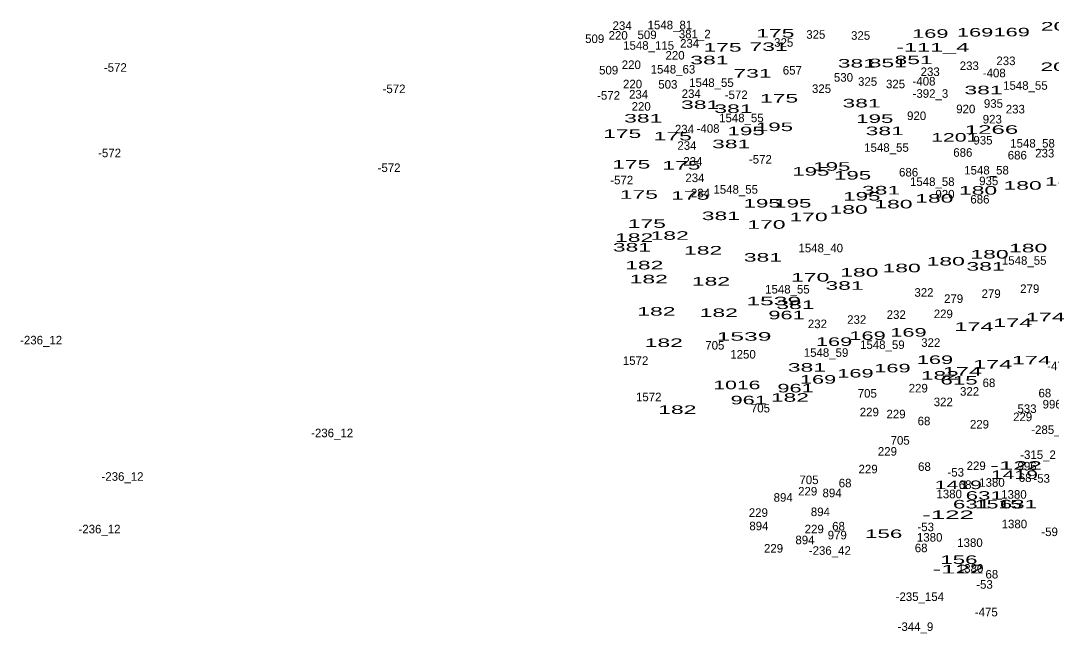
# Model space of a CAD drawing. Extents: x -660434 to -656144, y -997850 to -994016.
# Drawn here: x -658899.6 to -658418.1, y -996780.7 to -996494.1 of the extents above; entities that cross this region are included whole.
import ezdxf
from ezdxf.enums import TextEntityAlignment as Align

# ---------------------------------------------------------------- set-up
doc = ezdxf.new("R2010")
doc.units = 0
doc.header["$LTSCALE"] = 1.6
doc.layers.add('24', color=7, linetype='Continuous')

msp = doc.modelspace()

# ---------------------------------------------------------------- texts
at = {"layer": '24'}
for s, p in [('234', (-658618.631, -996498.49)), ('1548_81', (-658596.316, -996498.19)), ('220', (-658620.491, -996503.04)), ('509', (-658606.977, -996502.78)), ('381_2', (-658584.709, -996502.41)), ('325', (-658528.167, -996502.62)), ('325', (-658507.237, -996503.1)), ('509', (-658631.457, -996504.61)), ('1548_115', (-658606.27, -996507.76)), ('234', (-658587.101, -996506.76)), ('325', (-658543.147, -996506.37)), ('220', (-658593.901, -996512.36)), ('220', (-658614.341, -996516.77)), ('233', (-658456.467, -996517.26)), ('233', (-658439.357, -996514.95)), ('-572', (-658855.371, -996518.06)), ('509', (-658624.937, -996519.31)), ('1548_63', (-658594.887, -996518.87)), ('657', (-658539.128, -996519.38)), ('233', (-658474.727, -996520.05)), ('-408', (-658444.803, -996520.64)), ('220', (-658613.771, -996525.8)), ('503', (-658597.271, -996525.95)), ('1548_55', (-658576.902, -996525.14)), ('530', (-658515.231, -996522.69)), ('325', (-658503.977, -996524.62)), ('325', (-658490.917, -996525.77)), ('-408', (-658477.633, -996524.48)), ('1548_55', (-658430.252, -996526.48)), ('-572', (-658725.191, -996528.04)), ('-572', (-658624.961, -996531.12)), ('234', (-658610.941, -996530.59)), ('234', (-658586.341, -996530.3)), ('-572', (-658565.341, -996530.83)), ('325', (-658525.487, -996527.98)), ('-392_3', (-658474.628, -996530.23)), ('220', (-658609.741, -996536.27)), ('935', (-658445.183, -996534.89)), ('1548_55', (-658562.922, -996541.65)), ('920', (-658481.067, -996540.63)), ('920', (-658458.107, -996537.45)), ('233', (-658434.957, -996537.54)), ('-408', (-658578.483, -996546.57)), ('923', (-658445.703, -996542.24)), ('234', (-658589.531, -996546.87)), ('234', (-658588.371, -996554.56)), ('1548_55', (-658495.142, -996555.48)), ('935', (-658450.073, -996552.08)), ('1548_58', (-658426.922, -996553.5)), ('-572', (-658858.061, -996558.01)), ('-572', (-658554.051, -996560.98)), ('686', (-658459.478, -996557.81)), ('686', (-658434.038, -996559.06)), ('233', (-658421.217, -996558.12)), ('-572', (-658727.501, -996564.92)), ('234', (-658585.581, -996561.96)), ('-572', (-658618.821, -996570.69)), ('234', (-658584.631, -996569.66)), ('686', (-658484.818, -996567.03)), ('1548_58', (-658448.412, -996566.08)), ('1548_55', (-658565.572, -996575.08)), ('1548_58', (-658473.752, -996571.45)), ('935', (-658447.383, -996571.1)), ('234', (-658582.041, -996576.78)), ('920', (-658467.817, -996577.31)), ('686', (-658451.508, -996579.66)), ('1548_40', (-658525.861, -996602.5)), ('1548_55', (-658430.822, -996608.3)), ('1548_55', (-658541.422, -996621.75)), ('322', (-658477.637, -996623.26)), ('279', (-658428.218, -996621.48)), ('279', (-658463.788, -996626.14)), ('279', (-658446.248, -996623.81)), ('229', (-658468.603, -996633.26)), ('232', (-658527.407, -996637.94)), ('232', (-658509.047, -996635.92)), ('232', (-658490.587, -996633.61)), ('-236_12', (-658890.041, -996645.54)), ('1548_59', (-658497.067, -996647.7)), ('322', (-658474.467, -996646.69)), ('705', (-658575.327, -996647.96)), ('1250', (-658562.154, -996652.17)), ('1548_59', (-658523.377, -996651.35)), ('1572', (-658612.356, -996655.11)), ('-475', (-658414.735, -996657.65)), ('68', (-658447.273, -996665.5)), ('705', (-658504.117, -996670.43)), ('229', (-658480.313, -996668.01)), ('322', (-658456.327, -996669.53)), ('68', (-658421.163, -996670.3)), ('1572', (-658606.216, -996672.11)), ('322', (-658468.617, -996674.43)), ('996', (-658417.753, -996675.49)), ('705', (-658554.017, -996677.35)), ('229', (-658503.163, -996679.15)), ('229', (-658490.683, -996680.11)), ('229', (-658431.543, -996681.42)), ('533', (-658429.497, -996677.61)), ('68', (-658477.613, -996683.36)), ('229', (-658451.703, -996684.88)), ('-236_12', (-658754.101, -996688.95)), ('-285_12', (-658417.705, -996687.42)), ('705', (-658488.757, -996692.43)), ('229', (-658494.713, -996697.56)), ('-315_2', (-658424.356, -996699.12)), ('68', (-658477.423, -996704.68)), ('229', (-658453.243, -996704.28)), ('996', (-658429.463, -996704.49)), ('-236_12', (-658852.021, -996709.31)), ('229', (-658503.733, -996705.82)), ('-53', (-658462.795, -996707.34)), ('68', (-658430.383, -996709.87)), ('-53', (-658422.665, -996710.22)), ('705', (-658531.357, -996710.87)), ('68', (-658514.473, -996712.36)), ('68', (-658458.413, -996713.13)), ('1380', (-658445.874, -996712.11)), ('894', (-658543.407, -996719.1)), ('229', (-658531.963, -996716.19)), ('894', (-658520.557, -996716.99)), ('1380', (-658465.844, -996717.49)), ('1380', (-658435.604, -996717.69)), ('229', (-658555.003, -996726.18)), ('894', (-658526.027, -996725.82)), ('-236_12', (-658862.771, -996733.89)), ('894', (-658554.737, -996732.45)), ('229', (-658528.893, -996733.86)), ('68', (-658517.553, -996732.53)), ('-53', (-658476.815, -996732.89)), ('1380', (-658435.404, -996731.52)), ('894', (-658533.227, -996738.98)), ('979', (-658518.143, -996736.71)), ('1380', (-658474.964, -996737.76)), ('-59', (-658418.95, -996735.17)), ('229', (-658547.903, -996742.89)), ('-236_42', (-658521.611, -996743.93)), ('68', (-658478.953, -996742.71)), ('1380', (-658456.144, -996740.24)), ('1380', (-658455.854, -996752.26)), ('68', (-658445.933, -996755)), ('-53', (-658449.355, -996759.78)), ('-235_154', (-658479.559, -996765.51)), ('-475', (-658448.525, -996772.71)), ('-344_9', (-658481.616, -996779.52))]:
    msp.add_text(s, height=4, dxfattribs=at).set_placement(p, align=Align.CENTER)
for s, width, p in [('175', 2, (-658547.063, -996502.02)), ('169', 1.9, (-658474.667, -996502.18)), ('169', 1.9, (-658453.747, -996501.6)), ('169', 1.9, (-658436.657, -996501.5)), ('201', 2, (-658414.134, -996498.78)), ('175', 2, (-658571.733, -996508.65)), ('731', 2, (-658550.213, -996508.33)), ('-111_4', 2.05, (-658473.569, -996508.59)), ('381', 2, (-658577.867, -996514.57)), ('381', 2, (-658508.997, -996516.1)), ('851', 2, (-658494.527, -996515.94)), ('851', 2, (-658482.477, -996514.5)), ('201', 2, (-658414.324, -996517.7)), ('731', 2, (-658557.743, -996520.77)), ('381', 2, (-658449.807, -996528.59)), ('381', 2, (-658582.187, -996535.45)), ('175', 2, (-658545.333, -996532.46)), ('381', 2, (-658506.787, -996534.74)), ('381', 2, (-658608.777, -996541.79)), ('381', 2, (-658566.637, -996537.33)), ('195', 1.95, (-658547.463, -996545.8)), ('195', 1.95, (-658500.613, -996541.96)), ('175', 2, (-658618.603, -996549.01)), ('175', 2, (-658594.983, -996550.15)), ('195', 1.95, (-658560.713, -996547.72)), ('381', 2, (-658495.957, -996547.7)), ('1201', 1.85, (-658463.25, -996550.72)), ('1266', 2.1, (-658446.087, -996547.07)), ('381', 2, (-658567.697, -996553.8)), ('175', 2, (-658614.383, -996563.32)), ('175', 2, (-658590.953, -996563.79)), ('195', 1.95, (-658520.673, -996564.34)), ('195', 1.95, (-658530.473, -996566.64)), ('195', 1.95, (-658510.983, -996568.46)), ('381', 2, (-658497.677, -996575.43)), ('180', 2, (-658452.384, -996575.52)), ('180', 2, (-658431.554, -996573.21)), ('180', 2, (-658412.254, -996571.29)), ('175', 2, (-658610.823, -996577.44)), ('175', 2, (-658586.823, -996577.9)), ('195', 1.95, (-658506.663, -996578.26)), ('180', 2, (-658472.804, -996579.26)), ('195', 1.95, (-658553.223, -996581.53)), ('195', 1.95, (-658538.913, -996581.53)), ('180', 2, (-658512.834, -996584.45)), ('180', 2, (-658491.904, -996581.95)), ('381', 2, (-658572.497, -996587.41)), ('170', 2, (-658531.549, -996587.92)), ('175', 2, (-658607.083, -996591.06)), ('170', 2, (-658551.229, -996591.47)), ('182', 2, (-658613.017, -996597.6)), ('182', 2, (-658596.417, -996596.63)), ('381', 2, (-658614.057, -996602.1)), ('182', 2, (-658580.787, -996603.54)), ('180', 2, (-658428.964, -996602.5)), ('381', 2, (-658552.857, -996606.84)), ('180', 2, (-658467.464, -996608.65)), ('180', 2, (-658447.014, -996605.38)), ('182', 2, (-658608.307, -996610.47)), ('180', 2, (-658507.834, -996613.83)), ('180', 2, (-658488.064, -996611.82)), ('381', 2, (-658448.877, -996611.07)), ('182', 2, (-658606.197, -996617)), ('182', 2, (-658577.137, -996618.04)), ('170', 2, (-658530.789, -996616.16)), ('381', 2, (-658514.747, -996620)), ('1539', 2.15, (-658547.813, -996627.25)), ('182', 2, (-658602.647, -996632.08)), ('182', 2, (-658573.487, -996632.73)), ('381', 2, (-658537.687, -996629.01)), ('961', 1.9, (-658541.837, -996633.8)), ('174', 2.05, (-658436.158, -996637.42)), ('174', 2.05, (-658420.988, -996634.73)), ('169', 1.9, (-658484.877, -996641.92)), ('174', 2.05, (-658454.298, -996639.24)), ('182', 2, (-658599.187, -996646.75)), ('1539', 2.15, (-658561.693, -996643.82)), ('169', 1.9, (-658519.627, -996646.24)), ('169', 1.9, (-658503.987, -996643.45)), ('169', 1.9, (-658472.497, -996654.69)), ('174', 2.05, (-658445.568, -996656.82)), ('174', 2.05, (-658427.418, -996654.9)), ('381', 2, (-658532.307, -996658.3)), ('169', 1.9, (-658509.647, -996661.03)), ('169', 1.9, (-658492.367, -996658.63)), ('182', 2, (-658470.197, -996662.04)), ('174', 2.05, (-658459.668, -996660.14)), ('1016', 1.85, (-658565.025, -996666.49)), ('169', 1.9, (-658527.117, -996663.91)), ('615', 1.95, (-658461.243, -996664.3)), ('961', 1.9, (-658537.617, -996667.99)), ('961', 1.9, (-658559.507, -996673.56)), ('182', 2, (-658540.277, -996672.36)), ('182', 2, (-658592.857, -996678.03)), ('-122', 2.25, (-658434.611, -996704.15)), ('1419', 1.85, (-658435.385, -996708.49)), ('1419', 1.85, (-658461.595, -996713.2)), ('631', 1.95, (-658449.453, -996718.17)), ('631', 1.95, (-658455.403, -996722.25)), ('1515', 1.85, (-658442.844, -996722.23)), ('631', 1.95, (-658433.533, -996722.23)), ('-122', 2.25, (-658466.391, -996727.2)), ('156', 1.95, (-658496.453, -996736.09)), ('156', 1.95, (-658461.313, -996748.2)), ('-122', 2.25, (-658461.591, -996752.65))]:
    msp.add_text(s, height=4, dxfattribs=dict(at, width=width)).set_placement(p, align=Align.CENTER)

doc.saveas('drawing.dxf')
